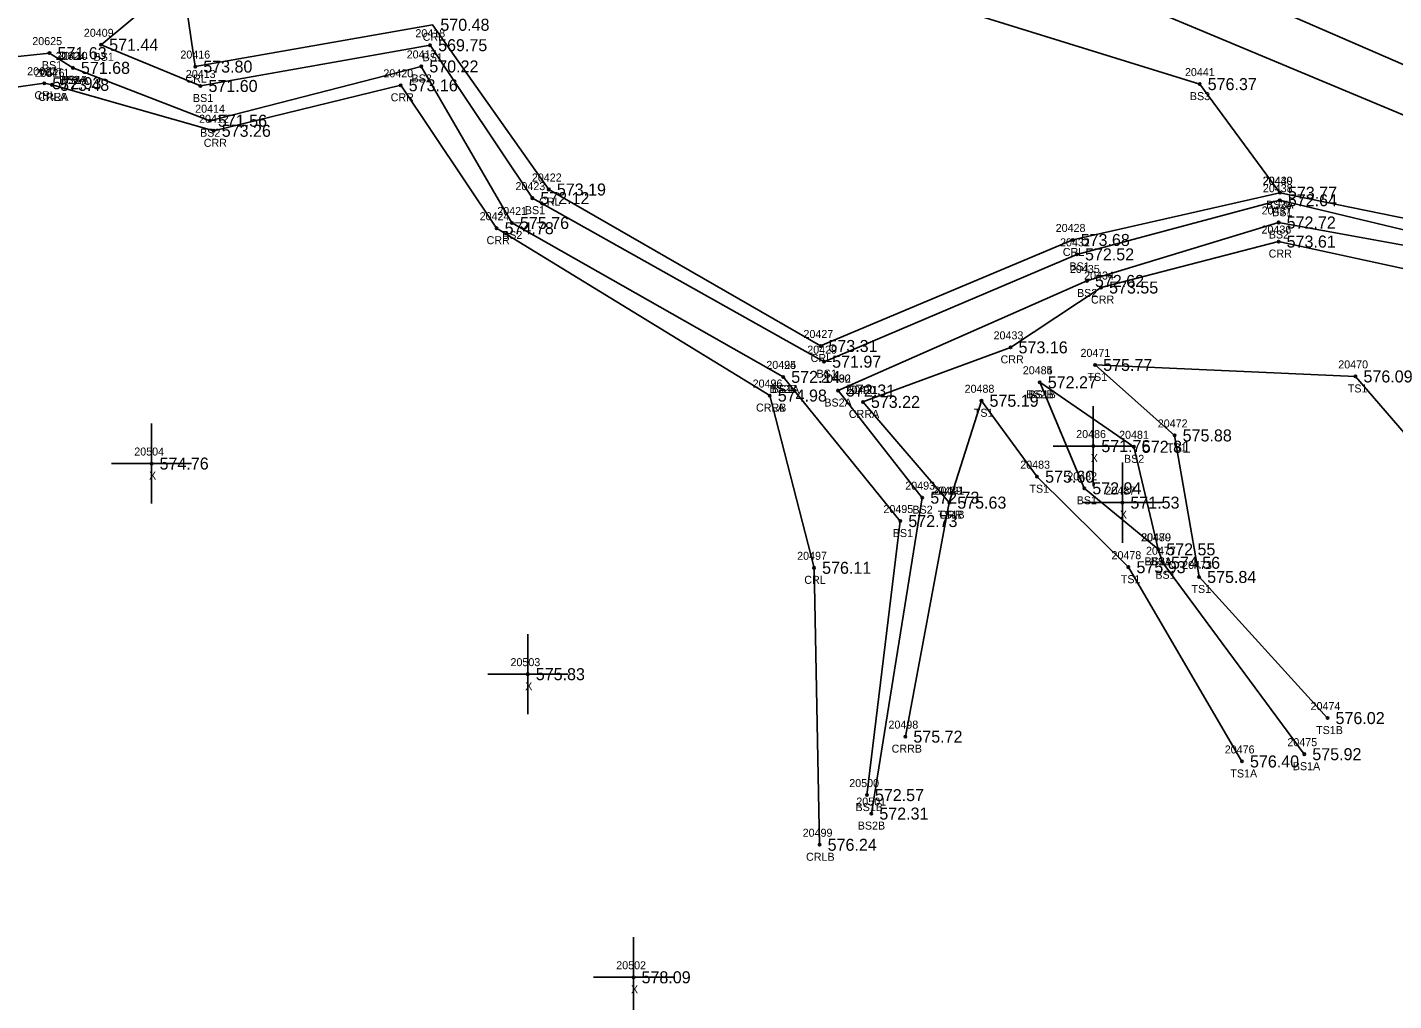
# Model space of a CAD drawing. Extents: x 1664837 to 1666270, y 987403 to 988245.
# Drawn here: x 1665462.9 to 1665633.6, y 987584.2 to 987705.8 of the extents above; entities that cross this region are included whole.
import ezdxf

# ---------------------------------------------------------------- set-up
doc = ezdxf.new("R2010")
doc.units = 0
for name, color, linetype in [('RD_DTM_BkLn2', 7, 'Continuous'), ('RD_DTM_BkLn_txCode', 7, 'Continuous'), ('RD_EX_H2O', 7, 'Continuous'), ('RD_EX_H2O_txCode', 7, 'Continuous'), ('RD_EX_Misc', 7, 'Continuous'), ('RD_EX_Misc_txCode', 7, 'Continuous'), ('RD_EX_Road', 7, 'Continuous'), ('RD_EX_TX_H2O_ELEV', 7, 'Continuous'), ('RD_EX_TX_Misc_ELEV', 7, 'Continuous'), ('RD_SMD_Locator', 7, 'Continuous')]:
    doc.layers.add(name, color=color, linetype=linetype)

msp = doc.modelspace()

# ---------------------------------------------------------------- linework, layer by layer
at = {"layer": 'RD_DTM_BkLn2'}
for points in [[(1665521.8, 987775.03), (1665513.35, 987762.3), (1665512.93, 987744.69), (1665504.21, 987730.32), (1665472.11, 987703.59), (1665484.52, 987698.45), (1665513.21, 987703.54), (1665525.98, 987684.44), (1665562.43, 987664.02), (1665594.02, 987677.42), (1665619.36, 987684.18), (1665641.6, 987678.85), (1665662.25, 987650.14), (1665684.59, 987631.79), (1665704.75, 987626.25), (1665722.78, 987589.94)], [(1666152.82, 987476.83), (1666108.53, 987496.54), (1666062.68, 987516.61), (1666015.91, 987535.8), (1665969.55, 987555.16), (1665926.09, 987572.12), (1665875.73, 987592.3), (1665829.7, 987613.88), (1665783.86, 987631.56), (1665738.66, 987650.04), (1665693.22, 987670.26), (1665645.99, 987690.14), (1665601.24, 987708.82), (1665555.03, 987727.9), (1665522.94, 987740.22)], [(1665619.37, 987685.12), (1665609.35, 987698.68), (1665574.4, 987709.55), (1665544.98, 987724.05), (1665518.2, 987735.79)], [(1665468.58, 987700.71), (1665465.66, 987702.55), (1665430.48, 987698.85), (1665398.05, 987680.55), (1665367.06, 987661.74), (1665332.15, 987651.54), (1665283, 987639.17), (1665233.73, 987658.08), (1665210.97, 987648.76), (1665173.41, 987617.25), (1665124.74, 987609.31), (1665095.75, 987609.41), (1665057.17, 987591.87)], [(1665468.58, 987700.71), (1665485.7, 987694.11), (1665512.11, 987700.89), (1665523.43, 987681.34), (1665557.32, 987662.12)], [(1665564.17, 987660.42), (1665595.26, 987674.1), (1665619.21, 987681.4), (1665639.59, 987677.7), (1665660.21, 987648.3), (1665682.63, 987628.31), (1665700.98, 987623.14), (1665721.95, 987588.38)], [(1665702.85, 987577.16), (1665687.46, 987610.21), (1665653.08, 987634.09), (1665628.81, 987662.18), (1665596.29, 987663.62), (1665606.22, 987654.81), (1665609.28, 987637.14), (1665625.32, 987619.52)], [(1665557.32, 987662.12), (1665571.95, 987644.12), (1665567.77, 987609.9)], [(1665604.17, 987640.59), (1665601.12, 987653.39), (1665589.37, 987661.45)], [(1665622.42, 987615.01), (1665604.76, 987638.91), (1665604.17, 987640.59), (1665594.93, 987648.21), (1665589.37, 987661.45)], [(1665564.17, 987660.42), (1665574.69, 987647.04), (1665568.33, 987607.59)], [(1665614.63, 987614.1), (1665600.45, 987638.36), (1665589.04, 987649.66), (1665582.09, 987659.14), (1665578.06, 987646.42)]]:
    msp.add_lwpolyline(points, dxfattribs=at)
at = {"layer": 'RD_EX_H2O'}
for points in [[(1665524.71, 987748.93), (1665523.69, 987745.83), (1665522.12, 987740.87), (1665518.2, 987735.79), (1665482.82, 987708), (1665483.87, 987700.87), (1665513.49, 987706.09), (1665528.04, 987685.52), (1665561.97, 987665.98), (1665593.48, 987679.22), (1665619.37, 987685.12), (1665642.78, 987680.31), (1665663.97, 987651.85), (1665686.03, 987634.26), (1665705.62, 987627.98), (1665724.83, 987594.97)], [(1665465.98, 987698.59), (1665465.01, 987698.79), (1665432.65, 987694.17), (1665400.81, 987677.37), (1665370.11, 987653.55), (1665334.58, 987643.2), (1665283.82, 987631.84), (1665232.68, 987646.81), (1665216.29, 987640.35), (1665180.84, 987613.76), (1665127.14, 987605.7), (1665095.77, 987606.5), (1665062.74, 987586.14)], [(1665465.98, 987698.59), (1665486.18, 987692.85), (1665509.53, 987698.53), (1665521.52, 987680.69), (1665555.64, 987659.79)], [(1665567.27, 987659), (1665585.72, 987665.81), (1665597.03, 987673.28), (1665619.21, 987679.02), (1665636.86, 987675.2), (1665656.96, 987646.24), (1665680.5, 987626.23), (1665698.55, 987621.97), (1665717.6, 987587.14)], [(1665555.64, 987659.79), (1665561.18, 987638.28), (1665561.87, 987603.7)], [(1665567.27, 987659), (1665578.06, 987646.42), (1665572.58, 987617.2)]]:
    msp.add_lwpolyline(points, dxfattribs=at)
at = {"layer": 'RD_EX_Misc'}
for p, q in [((1665596.06, 987648.48), (1665596.06, 987658.48)), ((1665478.41, 987646.3), (1665478.41, 987656.3)), ((1665591.06, 987653.48), (1665601.06, 987653.48)), ((1665473.41, 987651.3), (1665483.41, 987651.3)), ((1665599.69, 987641.42), (1665599.69, 987651.42)), ((1665594.69, 987646.42), (1665604.69, 987646.42)), ((1665525.41, 987620), (1665525.41, 987630)), ((1665520.41, 987625), (1665530.41, 987625)), ((1665538.62, 987582.15), (1665538.62, 987592.15)), ((1665533.62, 987587.15), (1665543.62, 987587.15))]:
    msp.add_line(p, q, dxfattribs=at)
at = {"layer": 'RD_EX_Road'}
msp.add_lwpolyline([(1666156.67, 987480.61), (1666109.28, 987500.74), (1666063.55, 987520.04), (1666017.04, 987539.82), (1665971.11, 987559.14), (1665924.88, 987578.79), (1665879.5, 987597.89), (1665833.22, 987617.38), (1665786.91, 987636.81), (1665741.44, 987656.13), (1665695.81, 987675.2), (1665649.26, 987694.85), (1665603.56, 987714.71), (1665558.4, 987733.87), (1665524.71, 987748.93)], dxfattribs=at)
at = {"layer": 'RD_SMD_Locator'}
for centre in [(1665472.11, 987703.59), (1665513.21, 987703.54), (1665465.66, 987702.55), (1665468.58, 987700.71), (1665468.58, 987700.71), (1665483.87, 987700.87), (1665512.11, 987700.89), (1665465.01, 987698.79), (1665465.98, 987698.59), (1665465.98, 987698.59), (1665484.52, 987698.45), (1665509.53, 987698.53), (1665609.35, 987698.68), (1665485.7, 987694.11), (1665486.18, 987692.85), (1665528.04, 987685.52), (1665619.37, 987685.12), (1665619.37, 987685.12), (1665525.98, 987684.44), (1665619.36, 987684.18), (1665523.43, 987681.34), (1665619.21, 987681.4), (1665521.52, 987680.69), (1665593.48, 987679.22), (1665619.21, 987679.02), (1665594.02, 987677.42), (1665595.26, 987674.1), (1665597.03, 987673.28), (1665561.97, 987665.98), (1665585.72, 987665.81), (1665562.43, 987664.02), (1665596.29, 987663.62), (1665557.32, 987662.12), (1665557.32, 987662.12), (1665589.37, 987661.45), (1665589.37, 987661.45), (1665628.81, 987662.18), (1665555.64, 987659.79), (1665555.64, 987659.79), (1665564.17, 987660.42), (1665564.17, 987660.42), (1665567.27, 987659), (1665567.27, 987659), (1665582.09, 987659.14), (1665606.22, 987654.81), (1665596.06, 987653.48), (1665601.12, 987653.39), (1665478.41, 987651.3), (1665589.04, 987649.66), (1665574.69, 987647.04), (1665594.93, 987648.21), (1665578.06, 987646.42), (1665578.06, 987646.42), (1665599.69, 987646.42), (1665571.95, 987644.12), (1665604.17, 987640.59), (1665604.17, 987640.59), (1665604.76, 987638.91), (1665561.18, 987638.28), (1665600.45, 987638.36), (1665609.28, 987637.14), (1665525.41, 987625), (1665625.32, 987619.52), (1665572.58, 987617.2), (1665622.42, 987615.01), (1665614.63, 987614.1), (1665567.77, 987609.9), (1665568.33, 987607.59), (1665561.87, 987603.7), (1665538.62, 987587.15)]:
    msp.add_circle(centre, 0.15, dxfattribs=at)

# ---------------------------------------------------------------- texts
at = {"layer": 'RD_DTM_BkLn_txCode'}
for s, p in [('20409', (1665469.95, 987704.59)), ('20418', (1665511.37, 987704.54)), ('20625', (1665463.51, 987703.55)), ('20624', (1665466.44, 987701.71)), ('20410', (1665466.7, 987701.71)), ('BS1', (1665471.16, 987701.59)), ('20417', (1665510.28, 987701.89)), ('BS1', (1665512.26, 987701.54)), ('BS1', (1665464.71, 987700.55)), ('20413', (1665482.69, 987699.45)), ('20441', (1665607.51, 987699.68)), ('BS2A', (1665466.86, 987698.71)), ('BS1A', (1665467.14, 987698.71)), ('BS2', (1665510.88, 987698.89)), ('BS1', (1665483.58, 987696.45)), ('BS3', (1665608.12, 987696.68)), ('20414', (1665483.86, 987695.11)), ('BS2', (1665484.47, 987692.11)), ('20423', (1665523.87, 987685.44)), ('20440', (1665617.21, 987686.12)), ('20438', (1665617.24, 987685.18)), ('20421', (1665521.6, 987682.34)), ('BS1', (1665525.04, 987682.44)), ('20437', (1665617.09, 987682.4)), ('BS3A', (1665617.65, 987683.12)), ('BS1', (1665618.41, 987682.18)), ('BS2', (1665522.2, 987679.34)), ('BS2', (1665617.98, 987679.4)), ('20432', (1665591.9, 987678.42)), ('BS1', (1665593.08, 987675.42)), ('20435', (1665593.14, 987675.1)), ('BS2', (1665594.03, 987672.1)), ('20429', (1665560.32, 987665.02)), ('20471', (1665594.46, 987664.62)), ('20470', (1665626.66, 987663.18)), ('20425', (1665555.21, 987663.12)), ('20494', (1665555.21, 987663.12)), ('BS1', (1665561.49, 987662.02)), ('20484', (1665587.25, 987662.45)), ('20485', (1665587.25, 987662.45)), ('TS1', (1665595.33, 987661.62)), ('BS2B', (1665555.62, 987660.12)), ('BS1A', (1665555.89, 987660.12)), ('20430', (1665562.02, 987661.42)), ('20492', (1665562.05, 987661.42)), ('20488', (1665579.98, 987660.14)), ('TS1', (1665627.85, 987660.18)), ('BS2A', (1665562.46, 987658.42)), ('BS2A', (1665562.46, 987658.42)), ('BS2B', (1665587.67, 987659.45)), ('BS1B', (1665587.95, 987659.45)), ('TS1', (1665581.13, 987657.14)), ('20472', (1665604.11, 987655.81)), ('20481', (1665599.28, 987654.39)), ('BS2', (1665599.89, 987651.39)), ('TS1', (1665605.26, 987652.81)), ('20483', (1665586.93, 987650.66)), ('20493', (1665572.57, 987648.04)), ('20482', (1665592.81, 987649.21)), ('20489', (1665575.94, 987647.42)), ('TS1', (1665588.08, 987647.66)), ('BS1', (1665593.98, 987646.21)), ('20495', (1665569.84, 987645.12)), ('BS2', (1665573.46, 987645.04)), ('TS1B', (1665576.63, 987644.42)), ('BS1', (1665571.01, 987642.12)), ('20480', (1665602.01, 987641.59)), ('20479', (1665602.05, 987641.59)), ('20478', (1665598.33, 987639.36)), ('20477', (1665602.64, 987639.91)), ('BS2A', (1665602.46, 987638.59)), ('BS1', (1665603.23, 987638.59)), ('20473', (1665607.16, 987638.14)), ('TS1', (1665599.49, 987636.36)), ('BS1', (1665603.81, 987636.91)), ('TS1', (1665608.32, 987635.14)), ('20474', (1665623.2, 987620.52)), ('TS1B', (1665623.89, 987617.52)), ('20475', (1665620.3, 987616.01)), ('20476', (1665612.48, 987615.1)), ('TS1A', (1665613.18, 987612.1)), ('BS1A', (1665620.98, 987613.01)), ('20500', (1665565.57, 987610.9)), ('20501', (1665566.45, 987608.59)), ('BS1B', (1665566.35, 987607.9)), ('BS2B', (1665566.63, 987605.59))]:
    msp.add_text(s, height=1, dxfattribs=at).set_placement(p)
at = {"layer": 'RD_EX_H2O_txCode'}
for s, p in [('CRL', (1665512.27, 987704.09)), ('20416', (1665482.01, 987701.87)), ('20627', (1665462.87, 987699.79)), ('20626', (1665463.81, 987699.59)), ('20411', (1665464.43, 987699.59)), ('20420', (1665507.37, 987699.53)), ('CRL', (1665482.64, 987698.87)), ('CRL', (1665463.78, 987696.79)), ('CRRA', (1665464.24, 987696.59)), ('CRLA', (1665464.26, 987696.59)), ('CRR', (1665508.28, 987696.53)), ('20412', (1665484.34, 987693.85)), ('CRR', (1665484.93, 987690.85)), ('20422', (1665525.92, 987686.52)), ('20439', (1665617.25, 987686.12)), ('CRL', (1665526.81, 987683.52)), ('CRL', (1665618.14, 987683.12)), ('20424', (1665519.4, 987681.69)), ('CRR', (1665520.26, 987678.69)), ('20428', (1665591.36, 987680.22)), ('20436', (1665617.07, 987680.02)), ('CRL', (1665592.25, 987677.22)), ('CRR', (1665617.96, 987677.02)), ('20434', (1665594.91, 987674.28)), ('CRR', (1665595.77, 987671.28)), ('20427', (1665559.85, 987666.98)), ('20433', (1665583.6, 987666.81)), ('CRL', (1665560.74, 987663.98)), ('CRR', (1665584.47, 987663.81)), ('20426', (1665553.5, 987660.79)), ('20496', (1665553.5, 987660.79)), ('20490', (1665565.11, 987660)), ('20431', (1665565.43, 987660)), ('CRRB', (1665553.92, 987657.79)), ('CRLA', (1665553.93, 987657.79)), ('CRRA', (1665565.52, 987657)), ('CRRA', (1665565.52, 987657)), ('20491', (1665576.22, 987647.42)), ('CRR', (1665576.81, 987644.42)), ('20497', (1665559.06, 987639.28)), ('CRL', (1665559.95, 987636.28)), ('20498', (1665570.47, 987618.2)), ('CRRB', (1665570.86, 987615.2)), ('20499', (1665559.75, 987604.7)), ('CRLB', (1665560.17, 987601.7))]:
    msp.add_text(s, height=1, dxfattribs=at).set_placement(p)
at = {"layer": 'RD_EX_Misc_txCode'}
for s, p in [('20486', (1665593.92, 987654.48)), ('20504', (1665476.25, 987652.3)), ('X', (1665595.74, 987651.48)), ('X', (1665478.09, 987649.3)), ('20487', (1665597.57, 987647.42)), ('X', (1665599.37, 987644.42)), ('20503', (1665523.25, 987626)), ('X', (1665525.09, 987623)), ('20502', (1665536.46, 987588.15)), ('X', (1665538.3, 987585.15))]:
    msp.add_text(s, height=1, dxfattribs=at).set_placement(p)
at = {"layer": 'RD_EX_TX_H2O_ELEV'}
for s, p in [('570.48', (1665514.49, 987705.34)), ('573.80', (1665484.87, 987700.12)), ('572.93', (1665466.01, 987698.04)), ('573.48', (1665466.98, 987697.84)), ('573.48', (1665466.98, 987697.84)), ('573.16', (1665510.53, 987697.78)), ('573.26', (1665487.18, 987692.1)), ('573.19', (1665529.04, 987684.77)), ('573.77', (1665620.37, 987684.37)), ('574.78', (1665522.52, 987679.94)), ('573.68', (1665594.48, 987678.47)), ('573.61', (1665620.21, 987678.27)), ('573.55', (1665598.03, 987672.53)), ('573.31', (1665562.97, 987665.23)), ('573.16', (1665586.72, 987665.06)), ('574.98', (1665556.64, 987659.04)), ('574.98', (1665556.64, 987659.04)), ('573.22', (1665568.27, 987658.25)), ('573.22', (1665568.27, 987658.25)), ('575.63', (1665579.06, 987645.67)), ('576.11', (1665562.18, 987637.53)), ('575.72', (1665573.58, 987616.45)), ('576.24', (1665562.87, 987602.95))]:
    msp.add_text(s, height=1.5, dxfattribs=at).set_placement(p)
at = {"layer": 'RD_EX_TX_Misc_ELEV'}
for s, p in [('571.44', (1665473.11, 987702.84)), ('569.75', (1665514.21, 987702.79)), ('571.63', (1665466.66, 987701.8)), ('571.68', (1665469.58, 987699.96)), ('571.68', (1665469.58, 987699.96)), ('570.22', (1665513.11, 987700.14)), ('571.60', (1665485.52, 987697.7)), ('576.37', (1665610.35, 987697.93)), ('571.56', (1665486.7, 987693.36)), ('572.12', (1665526.98, 987683.69)), ('572.64', (1665620.36, 987683.43)), ('573.77', (1665620.37, 987684.37)), ('575.76', (1665524.43, 987680.59)), ('572.72', (1665620.21, 987680.65)), ('572.52', (1665595.02, 987676.67)), ('572.62', (1665596.26, 987673.35)), ('571.97', (1665563.43, 987663.27)), ('575.77', (1665597.29, 987662.87)), ('572.14', (1665558.32, 987661.37)), ('572.14', (1665558.32, 987661.37)), ('576.09', (1665629.81, 987661.43)), ('572.31', (1665565.17, 987659.67)), ('572.31', (1665565.17, 987659.67)), ('572.27', (1665590.37, 987660.7)), ('572.27', (1665590.37, 987660.7)), ('575.19', (1665583.09, 987658.39)), ('571.76', (1665597.06, 987652.73)), ('572.81', (1665602.12, 987652.64)), ('575.88', (1665607.22, 987654.06)), ('574.76', (1665479.41, 987650.55)), ('575.60', (1665590.04, 987648.91)), ('572.94', (1665595.93, 987647.46)), ('572.73', (1665575.69, 987646.29)), ('575.63', (1665579.06, 987645.67)), ('571.53', (1665600.69, 987645.67)), ('572.73', (1665572.95, 987643.37)), ('572.55', (1665605.17, 987639.84)), ('572.55', (1665605.17, 987639.84)), ('575.93', (1665601.45, 987637.61)), ('574.56', (1665605.76, 987638.16)), ('575.84', (1665610.28, 987636.39)), ('575.83', (1665526.41, 987624.25)), ('576.02', (1665626.32, 987618.77)), ('576.40', (1665615.63, 987613.35)), ('575.92', (1665623.42, 987614.26)), ('572.57', (1665568.77, 987609.15)), ('572.31', (1665569.33, 987606.84)), ('578.09', (1665539.62, 987586.4))]:
    msp.add_text(s, height=1.5, dxfattribs=at).set_placement(p)

doc.saveas('drawing.dxf')
